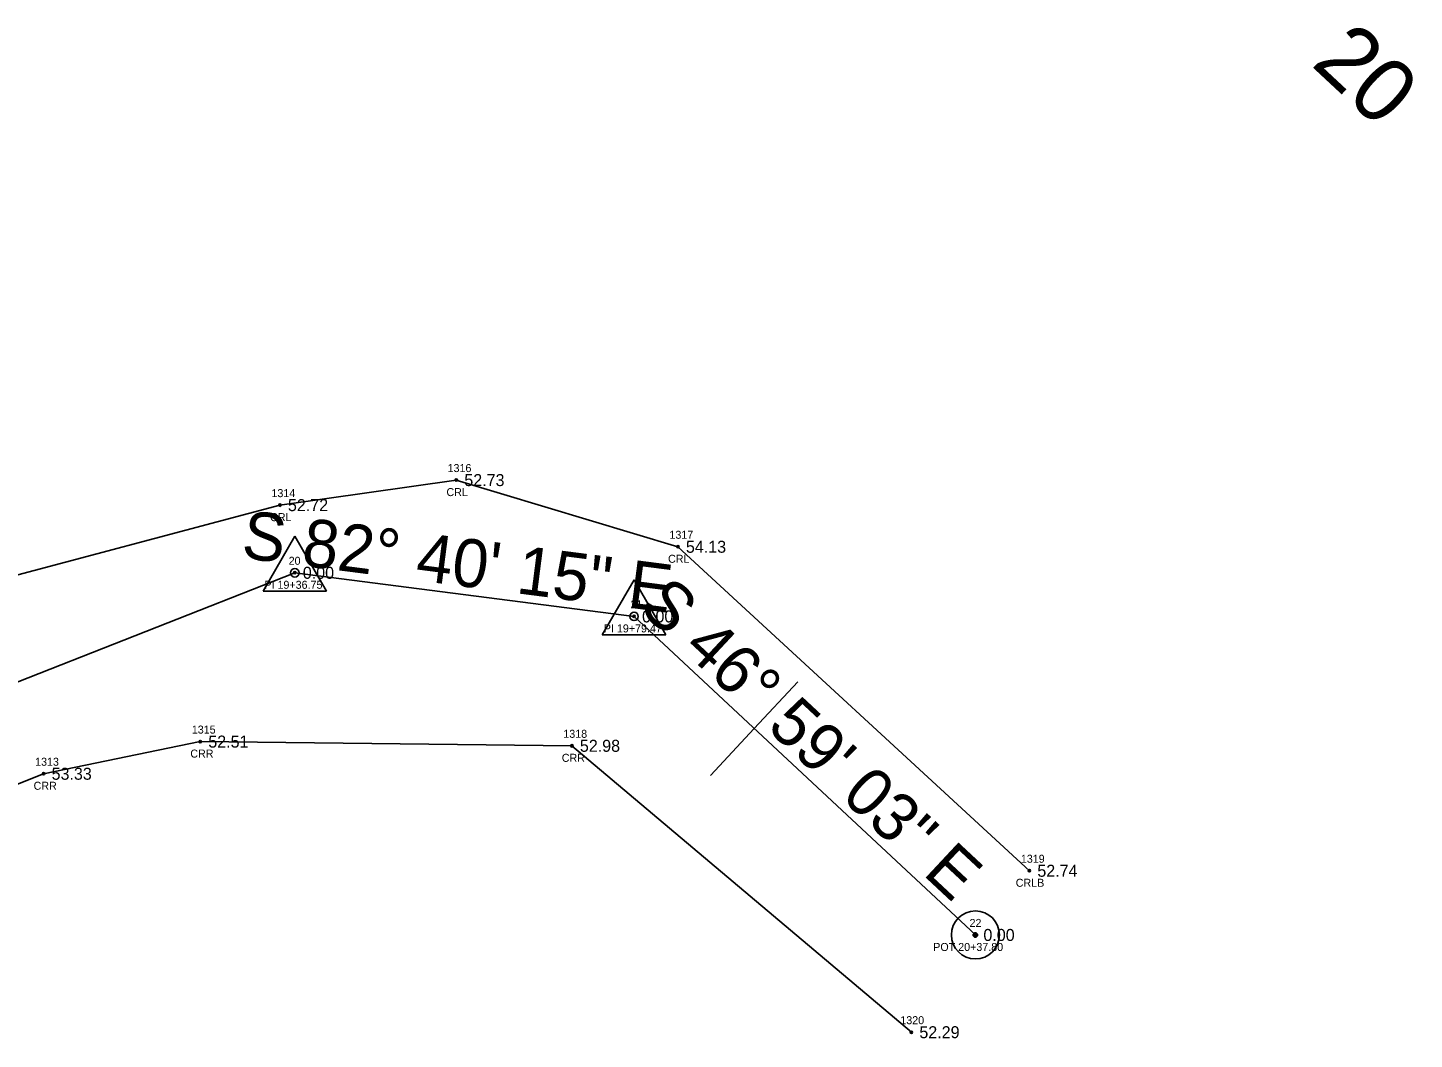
# Model space of a CAD drawing. Extents: x 2396531 to 2397633, y 770203 to 772837.
# Drawn here: x 2397415.9 to 2397589.2, y 771479.7 to 771606.1 of the extents above; entities that cross this region are included whole.
import ezdxf

# ---------------------------------------------------------------- set-up
doc = ezdxf.new("R2010")
doc.units = 0
for name, color, linetype in [('RD_EX_H2O', 7, 'Continuous'), ('RD_EX_H2O_txCode', 7, 'Continuous'), ('RD_EX_TX_H2O_ELEV', 7, 'Continuous'), ('RD_HC_Cl', 7, 'Continuous'), ('RD_HC_Data', 7, 'Continuous'), ('RD_HC_Data_Tic', 7, 'Continuous'), ('RD_HC_Survey_ELEV', 7, 'Continuous'), ('RD_HC_TX_Sta50', 7, 'Continuous'), ('RD_HC_txCode', 7, 'Continuous'), ('RD_SMD_Locator', 7, 'Continuous')]:
    doc.layers.add(name, color=color, linetype=linetype)

msp = doc.modelspace()

# ---------------------------------------------------------------- linework, layer by layer
at = {"layer": 'RD_EX_H2O'}
for points in [[(2397026.41, 771393.39), (2397070.16, 771405.14), (2397085.18, 771412.94), (2397115.64, 771424.52), (2397174.69, 771450.34), (2397230.25, 771466.48), (2397283.24, 771491.48), (2397342.91, 771519.42), (2397408.89, 771536.24), (2397447.46, 771546.47), (2397469.5, 771549.6), (2397497.19, 771541.27), (2397541.1, 771500.79)], [(2397041.52, 771355.95), (2397076.78, 771367.04), (2397074.45, 771374.78), (2397101.55, 771387.62), (2397127, 771397.33), (2397184.13, 771422.52), (2397239.58, 771440.33), (2397295.12, 771461.42), (2397353.86, 771487.36), (2397417.93, 771512.91), (2397437.51, 771516.93), (2397483.94, 771516.4), (2397526.36, 771480.62)]]:
    msp.add_lwpolyline(points, dxfattribs=at)
at = {"layer": 'RD_HC_Cl'}
for p, q in [((2396577.63, 771195.09), (2397449.32, 771538.02)), ((2397449.32, 771538.02), (2397491.71, 771532.57)), ((2397491.71, 771532.57), (2397534.36, 771492.77))]:
    msp.add_line(p, q, dxfattribs=at)
at = {"layer": 'RD_HC_Data'}
for p, q in [((2397445.35, 771535.73), (2397449.32, 771542.61)), ((2397449.32, 771542.61), (2397453.29, 771535.73)), ((2397487.74, 771530.27), (2397491.71, 771537.15)), ((2397491.71, 771537.15), (2397495.68, 771530.27)), ((2397445.35, 771535.73), (2397453.29, 771535.73)), ((2397487.74, 771530.27), (2397495.68, 771530.27))]:
    msp.add_line(p, q, dxfattribs=at)
for centre, radius in [((2397449.32, 771538.02), 0.529), ((2397491.71, 771532.57), 0.529), ((2397534.36, 771492.77), 3), ((2397534.36, 771492.77), 0.282)]:
    msp.add_circle(centre, radius, dxfattribs=at)
at = {"layer": 'RD_HC_Data_Tic'}
for q in [(2397512.19, 771524.41), (2397501.27, 771512.71)]:
    msp.add_line((2397506.73, 771518.56), q, dxfattribs=at)
at = {"layer": 'RD_SMD_Locator'}
for centre in [(2397469.5, 771549.6), (2397447.46, 771546.47), (2397497.19, 771541.27), (2397449.32, 771538.02), (2397491.71, 771532.57), (2397437.51, 771516.93), (2397483.94, 771516.4), (2397417.93, 771512.91), (2397541.1, 771500.79), (2397534.36, 771492.77), (2397526.36, 771480.62)]:
    msp.add_circle(centre, 0.15, dxfattribs=at)

# ---------------------------------------------------------------- texts
at = {"layer": 'RD_EX_H2O_txCode'}
for s, p in [('1316', (2397468.41, 771550.6)), ('1314', (2397446.4, 771547.47)), ('CRL', (2397468.27, 771547.6)), ('CRL', (2397446.23, 771544.47)), ('1317', (2397496.13, 771542.27)), ('CRL', (2397495.96, 771539.27)), ('1315', (2397436.45, 771517.93)), ('1318', (2397482.87, 771517.4)), ('1313', (2397416.87, 771513.91)), ('CRR', (2397436.26, 771514.93)), ('CRR', (2397482.68, 771514.4)), ('CRR', (2397416.68, 771510.91)), ('1319', (2397540.04, 771501.79)), ('CRLB', (2397539.4, 771498.79)), ('1320', (2397524.98, 771481.62))]:
    msp.add_text(s, height=1, dxfattribs=at).set_placement(p)
at = {"layer": 'RD_EX_TX_H2O_ELEV'}
for s, p in [('52.73', (2397470.5, 771548.85)), ('52.72', (2397448.46, 771545.72)), ('54.13', (2397498.19, 771540.52)), ('52.51', (2397438.51, 771516.18)), ('52.98', (2397484.94, 771515.65)), ('53.33', (2397418.93, 771512.16)), ('52.74', (2397542.1, 771500.04)), ('52.29', (2397527.36, 771479.87))]:
    msp.add_text(s, height=1.5, dxfattribs=at).set_placement(p)
at = {"layer": 'RD_HC_Data'}
for s, rotation, p in [('S 82%%d 40\' 15" E', 352.6708, (2397442.51, 771539.9)), ('S 46%%d 59\' 03" E', 316.9841, (2397492.11, 771533.56))]:
    msp.add_text(s, height=6, rotation=rotation, dxfattribs=at).set_placement(p)
at = {"layer": 'RD_HC_Survey_ELEV'}
for p in [(2397450.32, 771537.27), (2397492.71, 771531.82), (2397535.36, 771492.02)]:
    msp.add_text('0.00', height=1.5, dxfattribs=at).set_placement(p)
at = {"layer": 'RD_HC_TX_Sta50'}
msp.add_text('20', height=8, rotation=316.9841, dxfattribs=at).set_placement((2397576.17, 771601.48))
at = {"layer": 'RD_HC_txCode'}
for s, p in [('20', (2397448.55, 771539.02)), ('PI 19+36.75', (2397445.52, 771536.02)), ('21', (2397491.26, 771533.57)), ('PI 19+79.47', (2397487.93, 771530.57)), ('22', (2397533.63, 771493.77)), ('POT 20+37.80', (2397529.09, 771490.77))]:
    msp.add_text(s, height=1, dxfattribs=at).set_placement(p)

doc.saveas('drawing.dxf')
